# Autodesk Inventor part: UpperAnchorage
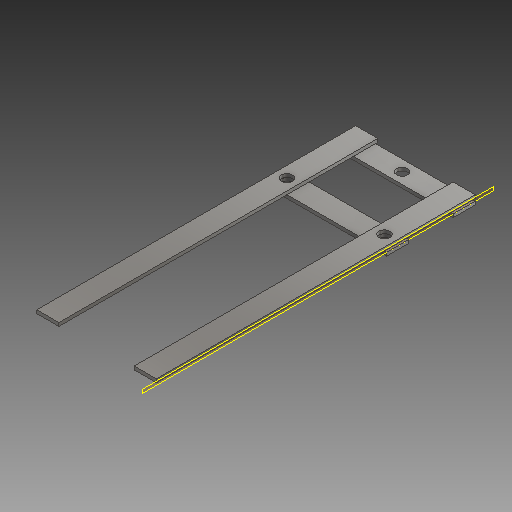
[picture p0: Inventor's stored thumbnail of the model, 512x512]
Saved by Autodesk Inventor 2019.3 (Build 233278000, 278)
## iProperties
Created: 2019-06
Part Number: UpperAnchorage
Material: Steel, Galvanized
Document SubType Name: Modeling
Designer: u1426
Density: 7.85 g/cm^3
Appearance: Galvanized
Author: u1426
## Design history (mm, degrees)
sketch "Sketch11"
  geometry: L1 (-107.95, 0)-(-171.45, 0); L2 (-171.45, 0)-(-171.45, -9.525); L3 (-171.45, -9.525)-(-107.95, -9.525); L4 (-107.95, -9.525)-(-107.95, 0); 1 further point
  constraints: 8 end point, 2 horizontal, 1 vertical
  dimensions: "d116" = 63.5 distance of L1.start L1.end; "d117" = 9.525 distance of L1.end L2.end; "d118" = 63.5 distance of L2.end L3.end; "d126" = 107.95 distance from line of point (0, 0) L4
extrude "Extrusion8" new body sketch "Sketch11" distance "d119" = 914.4; taper "d120" = 0 deg
sketch "Sketch12"
  geometry: L1 (-107.95, 0)-(-171.45, 0); L2 (-171.45, 0)-(-171.45, 9.525); L3 (-171.45, 9.525)-(-107.95, 9.525); L4 (-107.95, 9.525)-(-107.95, 0); 1 further point
  constraints: 8 end point, 2 horizontal, 1 vertical
  dimensions: "d121" = 63.5 distance of L1.start L1.end; "d122" = 9.525 distance of L1.end L2.end; "d123" = 63.5 distance of L2.end L3.end; "d127" = 107.95 distance from line of point (0, 0) L4
extrude "Extrusion9" new body sketch "Sketch12" distance "d124" = 914.4; taper "d125" = 0 deg
workplane "Work Plane2"
sketch "Sketch13"
  geometry: L1 (19.05, 844.55)-(19.05, 908.05); L2 (19.05, 908.05)-(9.525, 908.05); L3 (9.525, 908.05)-(9.525, 844.55); L4 (9.525, 844.55)-(19.05, 844.55); 2 further points
  constraints: 8 end point, 2 vertical, 1 horizontal
  dimensions: "d129" = 63.5 distance of L1.start L1.end; "d130" = 9.525 distance of L1.end L2.end; "d131" = 63.5 distance of L2.end L3.end; "d133" = 6.35 distance from line of point (0, 914.4) L2
extrude "Extrusion10" new body sketch "Sketch13" distance "d134" = 355.6; taper "d135" = 0 deg
sketch "Sketch14"
  geometry: L1 (0, 914.4)-(0, 0) reference; L2 (19.05, 717.55)-(9.525, 717.55); L3 (9.525, 717.55)-(9.525, 654.05); L4 (9.525, 654.05)-(19.05, 654.05); L5 (19.05, 654.05)-(19.05, 717.55); 1 further point
  constraints: 8 end point, 2 horizontal, 2 vertical
  dimensions: "d137" = 9.525 distance of L2.start L2.end; "d138" = 63.5 distance of L2.end L3.end; "d139" = 196.85 distance from line of L1.start L2
extrude "Extrusion11" new body sketch "Sketch14" distance "d140" = 355.6; taper "d141" = 0 deg
sketch "Sketch15"
  geometry: L1 (-355.6, 190.5)-(-355.6, 254) reference; L2 (0, 190.5)-(-355.6, 190.5) reference; L3 (0, 0)-(-355.6, 0) reference; L4 (-355.6, 0)-(-355.6, 63.5) reference; L5 (0, 63.5)-(0, 0) reference; 4 further points
  dimensions: "d149" = 177.8 distance from line of point (-177.8, 222.25) L1; "d150" = 31.75 distance from line of point (-177.8, 222.25) L2; "d151" = 31.75 distance from line of point (-317.5, 31.75) L3; "d152" = 31.75 distance from line of point (-38.1, 31.75) L3; "d153" = 38.1 distance from line of point (-317.5, 31.75) L4; "d154" = 38.1 distance from line of point (-38.1, 31.75) L5
hole "Hole3" sketch "Sketch15" at (-38.1, 31.75), (-317.5, 31.75), (-177.8, 222.25) diameter "d142" = 31.75; stored, may be unused: countersink angle "d146" = 82 deg, drill point angle "d148" = 118 deg; dims "d143" = 19.05, "d144" = 9.525, "d145" = 6.35, "d147" = 25.4
body "Solid6"
body "Solid7"
body "Solid8"
body "Solid9"
other parameters: "sa_0" = 4, "d128" = 6.35
